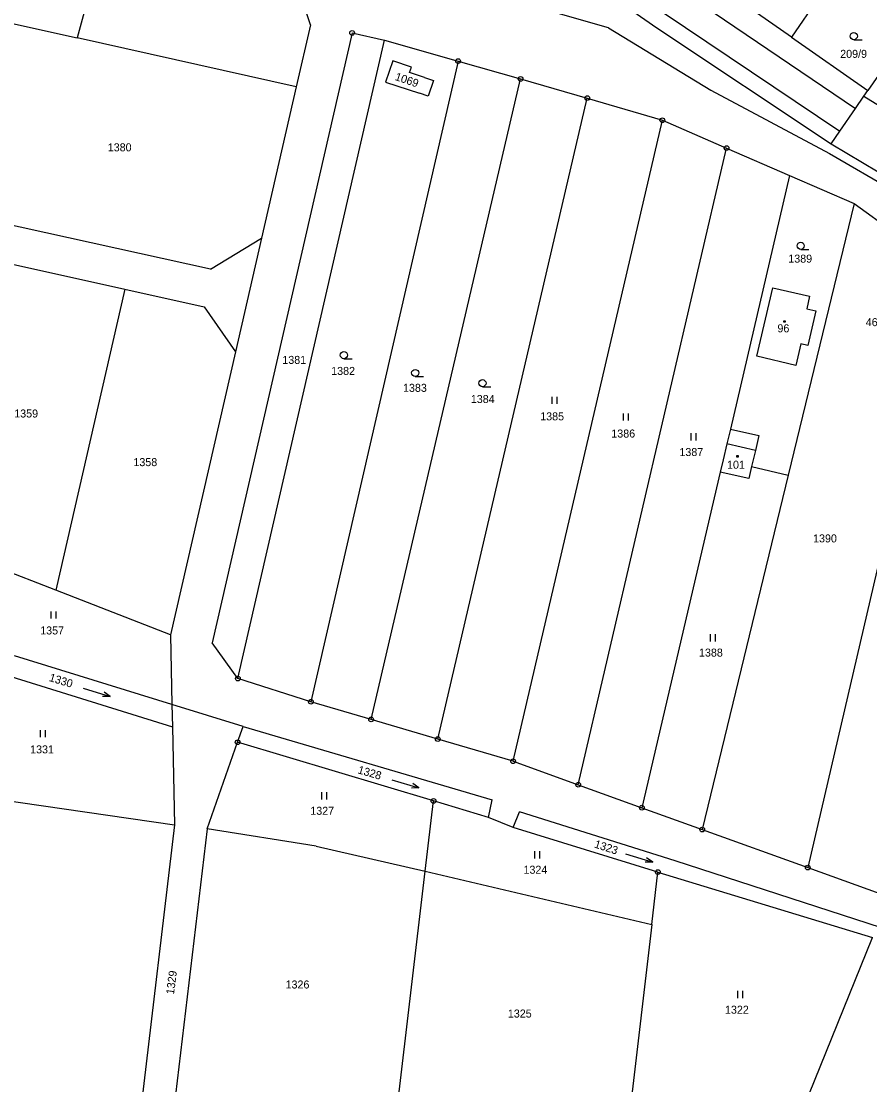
# Model space of a CAD drawing. Extents: x -796130 to -793145, y -1109506 to -1106267.
# Drawn here: x -794845 to -794664.8, y -1107830.1 to -1107604.2 of the extents above; entities that cross this region are included whole.
import ezdxf

# ---------------------------------------------------------------- set-up
doc = ezdxf.new("R2010")
doc.units = 0
for name, color, linetype in [('Vrstva 1', 7, 'Continuous'), ('Vrstva 14', 7, 'Continuous'), ('Vrstva 15', 7, 'Continuous'), ('Vrstva 16', 7, 'Continuous'), ('Vrstva 2', 7, 'Continuous'), ('Vrstva 23', 7, 'Continuous'), ('Vrstva 25', 7, 'Continuous'), ('Vrstva 28', 7, 'Continuous')]:
    doc.layers.add(name, color=color, linetype=linetype)

msp = doc.modelspace()

# ---------------------------------------------------------------- linework, layer by layer
at = {"layer": 'Vrstva 1'}
for p, q in [((-794824.63, -1107576.66), (-794833.09, -1107607.75)), ((-794735.95, -1107587.55), (-794710.01, -1107605.65)), ((-794681.46, -1107607.59), (-794698.42, -1107595.76)), ((-794783.56, -1107605.02), (-794785.81, -1107598.21)), ((-794675.74, -1107599.18), (-794681.46, -1107607.59)), ((-794720.31, -1107605.63), (-794740.92, -1107599.75)), ((-794848.09, -1107604.4), (-794833.09, -1107607.75)), ((-794783.56, -1107605.02), (-794786.58, -1107618.15)), ((-794720.31, -1107605.63), (-794698.55, -1107618.88)), ((-794710.01, -1107605.65), (-794673.06, -1107630.3)), ((-794786.58, -1107618.15), (-794833.09, -1107607.75)), ((-794774.72, -1107606.71), (-794804.45, -1107736.23)), ((-794798.98, -1107743.84), (-794767.85, -1107608.24)), ((-794774.72, -1107606.71), (-794767.85, -1107608.24)), ((-794767.85, -1107608.24), (-794752.23, -1107612.71)), ((-794681.46, -1107607.59), (-794665.24, -1107618.91)), ((-794752.23, -1107612.71), (-794783.47, -1107748.77)), ((-794766.11, -1107612.64), (-794767.63, -1107617.15)), ((-794762.13, -1107613.99), (-794766.11, -1107612.64)), ((-794752.23, -1107612.71), (-794738.98, -1107616.5)), ((-794660.1, -1107611.48), (-794665.24, -1107618.91)), ((-794762.52, -1107615.15), (-794762.13, -1107613.99)), ((-794759.35, -1107616.21), (-794762.52, -1107615.15)), ((-794770.69, -1107752.53), (-794738.98, -1107616.5)), ((-794767.63, -1107617.15), (-794760.45, -1107619.52)), ((-794759.35, -1107616.21), (-794757.44, -1107616.85)), ((-794757.44, -1107616.85), (-794758.56, -1107620.15)), ((-794738.98, -1107616.5), (-794724.81, -1107620.55)), ((-794786.58, -1107618.15), (-794793.97, -1107650.34)), ((-794758.56, -1107620.15), (-794760.45, -1107619.52)), ((-794698.55, -1107618.88), (-794673.39, -1107632.3)), ((-794666.1, -1107620.16), (-794665.24, -1107618.91)), ((-794756.54, -1107756.69), (-794724.81, -1107620.55)), ((-794724.81, -1107620.55), (-794708.87, -1107625.27)), ((-794667.89, -1107622.77), (-794666.1, -1107620.16)), ((-794666.1, -1107620.16), (-794660.96, -1107623.34)), ((-794671.21, -1107627.61), (-794667.89, -1107622.77)), ((-794740.56, -1107761.39), (-794708.87, -1107625.27)), ((-794708.87, -1107625.27), (-794695.23, -1107631.18)), ((-794673.06, -1107630.3), (-794671.21, -1107627.61)), ((-794673.06, -1107630.3), (-794653.57, -1107641.84)), ((-794726.72, -1107766.39), (-794695.23, -1107631.18)), ((-794695.23, -1107631.18), (-794681.84, -1107636.98)), ((-794673.39, -1107632.3), (-794653.29, -1107643.99)), ((-794681.84, -1107636.98), (-794694.43, -1107690.85)), ((-794681.84, -1107636.98), (-794668.13, -1107642.93)), ((-794668.13, -1107642.93), (-794682.14, -1107700.62)), ((-794668.13, -1107642.93), (-794656.4, -1107651.44)), ((-794804.82, -1107656.92), (-794857.47, -1107645.24)), ((-794804.82, -1107656.92), (-794793.97, -1107650.34)), ((-794793.97, -1107650.34), (-794799.49, -1107674.42)), ((-794851.43, -1107654.78), (-794822.97, -1107661.15)), ((-794822.97, -1107661.15), (-794837.64, -1107725.07)), ((-794822.97, -1107661.15), (-794806.1, -1107664.9)), ((-794688.81, -1107675.4), (-794685.42, -1107660.82)), ((-794685.42, -1107660.82), (-794677.6, -1107662.63)), ((-794677.6, -1107662.63), (-794678.2, -1107665.28)), ((-794806.1, -1107664.9), (-794799.49, -1107674.42)), ((-794678.2, -1107665.28), (-794676.29, -1107665.76)), ((-794676.29, -1107665.76), (-794678, -1107673.08)), ((-794679.46, -1107672.76), (-794680.54, -1107677.37)), ((-794678, -1107673.08), (-794679.46, -1107672.76)), ((-794799.49, -1107674.42), (-794813.3, -1107734.57)), ((-794680.54, -1107677.37), (-794688.81, -1107675.4)), ((-794694.43, -1107690.85), (-794695.17, -1107694.01)), ((-794694.43, -1107690.85), (-794688.42, -1107692.23)), ((-794695.17, -1107694.01), (-794695.96, -1107697.39)), ((-794688.42, -1107692.23), (-794689.12, -1107695.38)), ((-794689.12, -1107695.38), (-794689.93, -1107698.8)), ((-794695.96, -1107697.39), (-794696.57, -1107700)), ((-794696.57, -1107700), (-794713.22, -1107771.26)), ((-794682.14, -1107700.62), (-794700.4, -1107775.9)), ((-794690.54, -1107701.38), (-794696.57, -1107700)), ((-794689.93, -1107698.8), (-794690.54, -1107701.38)), ((-794689.93, -1107698.8), (-794682.14, -1107700.62)), ((-794659.77, -1107705.73), (-794678, -1107783.99)), ((-794837.64, -1107725.07), (-794850.4, -1107720.09)), ((-794813.3, -1107734.57), (-794837.64, -1107725.07)), ((-794813.3, -1107734.57), (-794812.99, -1107749.33)), ((-794798.98, -1107743.84), (-794804.45, -1107736.23)), ((-794812.99, -1107749.33), (-794846.38, -1107739.04)), ((-794847.19, -1107743.39), (-794812.88, -1107754.1)), ((-794783.47, -1107748.77), (-794798.98, -1107743.84)), ((-794797.85, -1107753.99), (-794812.99, -1107749.33)), ((-794812.99, -1107749.33), (-794812.88, -1107754.1)), ((-794770.69, -1107752.53), (-794783.47, -1107748.77)), ((-794756.54, -1107756.69), (-794770.69, -1107752.53)), ((-794812.88, -1107754.1), (-794812.44, -1107774.92)), ((-794799.03, -1107757.37), (-794797.85, -1107753.99)), ((-794797.85, -1107753.99), (-794745.02, -1107769.57)), ((-794805.49, -1107775.74), (-794799.03, -1107757.37)), ((-794757.45, -1107769.82), (-794799.03, -1107757.37)), ((-794740.56, -1107761.39), (-794756.54, -1107756.69)), ((-794740.56, -1107761.39), (-794726.72, -1107766.39)), ((-794726.72, -1107766.39), (-794713.22, -1107771.26)), ((-794868.83, -1107766.68), (-794812.44, -1107774.92)), ((-794759.22, -1107784.77), (-794757.45, -1107769.82)), ((-794745.74, -1107773.32), (-794757.45, -1107769.82)), ((-794745.74, -1107773.32), (-794745.02, -1107769.57)), ((-794740.51, -1107775.47), (-794739.22, -1107772.11)), ((-794706.14, -1107782.56), (-794739.22, -1107772.11)), ((-794713.22, -1107771.26), (-794700.4, -1107775.9)), ((-794812.44, -1107774.92), (-794821.91, -1107854.92)), ((-794740.51, -1107775.47), (-794745.74, -1107773.32)), ((-794709.81, -1107784.95), (-794740.51, -1107775.47)), ((-794805.49, -1107775.74), (-794814.66, -1107853)), ((-794782.35, -1107779.4), (-794805.49, -1107775.74)), ((-794700.4, -1107775.9), (-794678, -1107783.99)), ((-794782.35, -1107779.4), (-794759.22, -1107784.77)), ((-794659.34, -1107797.79), (-794706.14, -1107782.56)), ((-794678, -1107783.99), (-794662.7, -1107789.52)), ((-794765.64, -1107838.94), (-794759.22, -1107784.77)), ((-794759.22, -1107784.77), (-794711.11, -1107796.1)), ((-794711.11, -1107796.1), (-794709.81, -1107784.95)), ((-794709.81, -1107784.95), (-794664.25, -1107798.84)), ((-794711.11, -1107796.1), (-794716.25, -1107840.09)), ((-794680.15, -1107838.09), (-794664.25, -1107798.84))]:
    msp.add_line(p, q, dxfattribs=at)
at = {"layer": 'Vrstva 2'}
for p, q in [((-794734.8, -1107577.36), (-794667.89, -1107622.77)), ((-794736.64, -1107583.51), (-794671.21, -1107627.61)), ((-794689.12, -1107695.38), (-794695.17, -1107694.01))]:
    msp.add_line(p, q, dxfattribs=at)
at = {"layer": 'Vrstva 23'}
for p, q in [((-794668.22, -1107608.15), (-794666.47, -1107608.15)), ((-794679.49, -1107652.68), (-794677.74, -1107652.68)), ((-794776.48, -1107675.9), (-794774.73, -1107675.9)), ((-794761.34, -1107679.68), (-794759.59, -1107679.68)), ((-794747.05, -1107681.85), (-794745.3, -1107681.85)), ((-794732.27, -1107685.47), (-794732.27, -1107683.97)), ((-794731.27, -1107683.97), (-794731.27, -1107685.47)), ((-794717.15, -1107689.06), (-794717.15, -1107687.56)), ((-794716.15, -1107687.56), (-794716.15, -1107689.06)), ((-794702.76, -1107693.25), (-794702.76, -1107691.75)), ((-794701.76, -1107691.75), (-794701.76, -1107693.25)), ((-794838.61, -1107731.09), (-794838.61, -1107729.59)), ((-794837.61, -1107729.59), (-794837.61, -1107731.09)), ((-794698.64, -1107735.94), (-794698.64, -1107734.44)), ((-794697.64, -1107734.44), (-794697.64, -1107735.94)), ((-794831.834, -1107745.858), (-794826.105, -1107747.641)), ((-794826.105, -1107747.641), (-794827.686, -1107747.673)), ((-794826.105, -1107747.641), (-794827.389, -1107746.718)), ((-794840.91, -1107756.3), (-794840.91, -1107754.8)), ((-794839.91, -1107754.8), (-794839.91, -1107756.3)), ((-794766.307, -1107765.34), (-794760.552, -1107767.039)), ((-794760.552, -1107767.039), (-794761.849, -1107766.135)), ((-794781.18, -1107769.49), (-794781.18, -1107767.99)), ((-794780.18, -1107767.99), (-794780.18, -1107769.49)), ((-794760.552, -1107767.039), (-794762.132, -1107767.094)), ((-794735.94, -1107782.03), (-794735.94, -1107780.53)), ((-794734.94, -1107780.53), (-794734.94, -1107782.03)), ((-794716.664, -1107781.092), (-794710.915, -1107782.807)), ((-794710.915, -1107782.807), (-794712.209, -1107781.899)), ((-794710.915, -1107782.807), (-794712.495, -1107782.857)), ((-794692.85, -1107811.69), (-794692.85, -1107810.19)), ((-794691.85, -1107810.19), (-794691.85, -1107811.69))]:
    msp.add_line(p, q, dxfattribs=at)
for centre in [(-794668.22, -1107607.4), (-794679.49, -1107651.93), (-794776.48, -1107675.15), (-794761.34, -1107678.93), (-794747.05, -1107681.1)]:
    msp.add_circle(centre, 0.75, dxfattribs=at)
at = {"layer": 'Vrstva 25'}
for p, q in [((-794683.06, -1107667.86), (-794682.76, -1107667.86)), ((-794683.06, -1107668.16), (-794683.06, -1107667.86)), ((-794682.76, -1107668.16), (-794683.06, -1107668.16)), ((-794682.76, -1107667.86), (-794682.76, -1107668.16)), ((-794693.05, -1107696.49), (-794692.75, -1107696.49)), ((-794693.05, -1107696.79), (-794693.05, -1107696.49)), ((-794692.75, -1107696.49), (-794692.75, -1107696.79)), ((-794692.75, -1107696.79), (-794693.05, -1107696.79))]:
    msp.add_line(p, q, dxfattribs=at)
at = {"layer": 'Vrstva 28'}
for centre, radius in [((-794774.72, -1107606.71), 0.5), ((-794774.72, -1107606.71), 0.01), ((-794752.23, -1107612.71), 0.5), ((-794752.23, -1107612.71), 0.01), ((-794738.98, -1107616.5), 0.5), ((-794738.98, -1107616.5), 0.01), ((-794724.81, -1107620.55), 0.5), ((-794724.81, -1107620.55), 0.01), ((-794708.87, -1107625.27), 0.5), ((-794708.87, -1107625.27), 0.01), ((-794695.23, -1107631.18), 0.5), ((-794695.23, -1107631.18), 0.01), ((-794798.98, -1107743.84), 0.5), ((-794798.98, -1107743.84), 0.01), ((-794783.47, -1107748.77), 0.5), ((-794783.47, -1107748.77), 0.01), ((-794770.69, -1107752.53), 0.5), ((-794770.69, -1107752.53), 0.01), ((-794799.03, -1107757.37), 0.5), ((-794799.03, -1107757.37), 0.01), ((-794756.54, -1107756.69), 0.5), ((-794756.54, -1107756.69), 0.01), ((-794740.56, -1107761.39), 0.5), ((-794740.56, -1107761.39), 0.01), ((-794726.72, -1107766.39), 0.5), ((-794726.72, -1107766.39), 0.01), ((-794757.45, -1107769.82), 0.5), ((-794757.45, -1107769.82), 0.01), ((-794713.22, -1107771.26), 0.5), ((-794713.22, -1107771.26), 0.01), ((-794700.4, -1107775.9), 0.5), ((-794700.4, -1107775.9), 0.01), ((-794709.81, -1107784.95), 0.5), ((-794678, -1107783.99), 0.5), ((-794678, -1107783.99), 0.01), ((-794709.81, -1107784.95), 0.01)]:
    msp.add_circle(centre, radius, dxfattribs=at)

# ---------------------------------------------------------------- texts
at = {"layer": 'Vrstva 14'}
for s, p in [('209/9', (-794671.11, -1107612.01)), ('1380', (-794826.599, -1107631.86)), ('1389', (-794682.13, -1107655.5)), ('1381', (-794789.543, -1107677.01)), ('1382', (-794779.169, -1107679.35)), ('1383', (-794763.92, -1107682.94)), ('1384', (-794749.526, -1107685.32)), ('1359', (-794846.456, -1107688.39)), ('1385', (-794734.796, -1107689)), ('1386', (-794719.7, -1107692.65)), ('1387', (-794705.246, -1107696.58)), ('1358', (-794821.156, -1107698.72)), ('1390', (-794676.869, -1107714.92)), ('1357', (-794840.943, -1107734.47)), ('1388', (-794701.089, -1107739.17)), ('1331', (-794843.083, -1107759.73)), ('1327', (-794783.606, -1107772.77)), ('1324', (-794738.346, -1107785.29)), ('1326', (-794788.85, -1107809.66)), ('1322', (-794695.569, -1107815.02)), ('1325', (-794741.666, -1107815.83))]:
    msp.add_text(s, height=1.7, dxfattribs=at).set_placement(p)
for s, rotation, p in [('1069', 341.1, (-794765.757, -1107616.676)), ('1330', 342.9, (-794839.178, -1107744.326)), ('1328', 343.8, (-794773.649, -1107763.93)), ('1323', 342, (-794723.449, -1107779.674)), ('1329', 82.8, (-794812.548, -1107810.995))]:
    msp.add_text(s, height=1.7, rotation=rotation, dxfattribs=at).set_placement(p)
at = {"layer": 'Vrstva 15'}
for s, p in [('96', (-794684.437, -1107670.3)), ('101', (-794695.132, -1107699.27))]:
    msp.add_text(s, height=1.7, dxfattribs=at).set_placement(p)
at = {"layer": 'Vrstva 16'}
msp.add_text('460/11', height=1.7, dxfattribs=at).set_placement((-794665.683, -1107668.99))

doc.saveas('drawing.dxf')
